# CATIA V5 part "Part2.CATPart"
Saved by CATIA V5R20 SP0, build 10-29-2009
Part number: Part2
Bounding box of the stored display mesh (mm): x -22.5 to 40, y -22.49 to 22.49, z 0 to 50
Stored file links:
  E:\Ehsan\Catia\Tamrin\Digital Mockup\1\Part2.CATPart
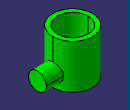
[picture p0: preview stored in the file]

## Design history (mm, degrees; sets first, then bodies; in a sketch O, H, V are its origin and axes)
Body1 (main body)
  Sketch1 on xy-plane, origin (0, 0, 0), H (1, 0, 0), V (0, 1, 0)
    circle A1 centre (0, 0) radius 17.5
    circle A2 centre (0, 0) radius 22.5
    radius A1 = 17.5
    radius A2 = 22.5
  Pad1: profile Sketch1, direction (0, 0, 1), length 50
  Plane1: type Offset, RefPlane yz-plane, Offset 40
  Sketch2 on Plane1, origin (40, 0, 0), H (0, 1, 0), V (0, 0, 1)
    circle A1 centre (0, 15) radius 10
    point P1 (0, 15)
    reference projected line E1 (-22.5, 50) -> (22.5, 50) from edge [face of Pad1 from Sketch1.A2 | end face of Pad1]
    radius A1 = 10
    distance A1 E1 = 25
    coincidence: P1 V
  Pad2: profile Sketch2, direction (-1, 0, 0), up to the existing solid (limit type 2)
